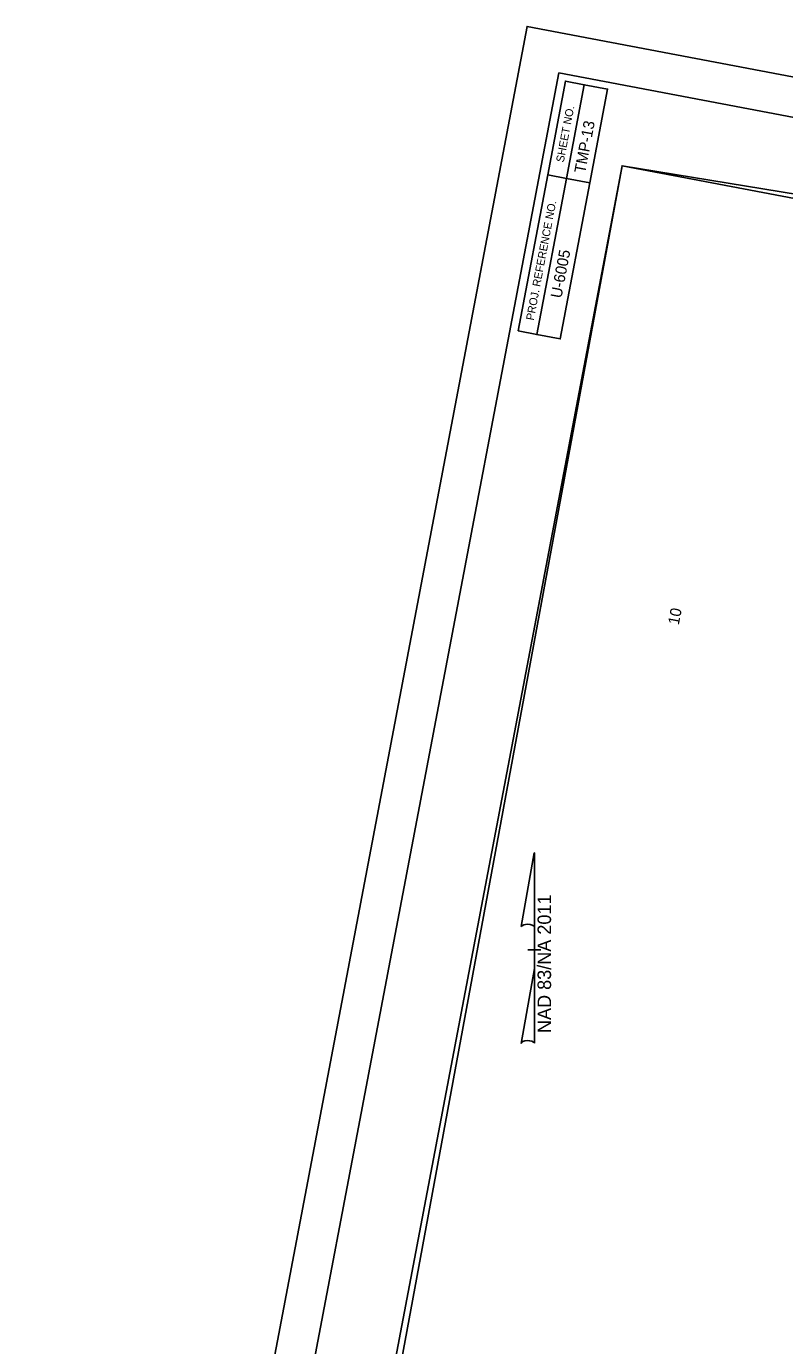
# Model space of a CAD drawing. Extents: x 1615680 to 1619687, y 899305 to 902270.
# Drawn here: x 1615680 to 1616157, y 900338 to 901168 of the extents above; entities that cross this region are included whole.
import ezdxf

# ---------------------------------------------------------------- set-up
doc = ezdxf.new("R2010")
doc.units = 0
for name, color, linetype in [('Prop Conc 2ft 6in Curb and Gutter', 7, 'Continuous'), ('Prop Conc 4in Sidewalk', 7, 'Continuous'), ('Scratch_Level_7', 7, 'Continuous'), ('Scratch_Level_8', 7, 'Continuous'), ('STAGE 3', 7, 'Continuous'), ('Stage 5', 7, 'Continuous')]:
    doc.layers.add(name, color=color, linetype=linetype)

msp = doc.modelspace()

# ---------------------------------------------------------------- linework, layer by layer
at = {"layer": 'Prop Conc 4in Sidewalk'}
msp.add_lwpolyline([(1616176.29, 901060.7), (1616848.46, 900914.27), (1616896.28, 900812.91), (1616872.94, 900688.21), (1616835.87, 900695.21), (1616753.94, 900262.18), (1616898.09, 900233.43), (1616734.79, 899562.1), (1616202.98, 899609.43), (1616198.71, 899647.14), (1615822.69, 899825.07), (1616054.34, 901080.76)], close=True, dxfattribs=at)
at = {"layer": 'Scratch_Level_7'}
msp.add_line((1616019.39, 901072.79), (1616030.58, 901131.73), dxfattribs=at)
for points in [[(1616014.55, 901139.21), (1615734.74, 899665.53), (1616766.32, 899469.67), (1617046.12, 900943.35)], [(1616019.39, 901072.79), (1616030.58, 901131.73), (1616018.79, 901133.97), (1616007.6, 901075.03)], [(1616019.39, 901072.79), (1616030.58, 901131.73), (1616045.31, 901128.94), (1616034.12, 901069.99)], [(1615988.94, 900976.78), (1616007.6, 901075.03), (1616019.39, 901072.79), (1616000.73, 900974.54)], [(1616019.39, 901072.79), (1616000.73, 900974.54), (1616015.47, 900971.74), (1616034.12, 901069.99)]]:
    msp.add_lwpolyline(points, close=True, dxfattribs=at)
at = {"layer": 'Scratch_Level_8'}
msp.add_lwpolyline([(1616054.34, 901080.76), (1615793.19, 899705.33), (1616726.52, 899528.12), (1616890.46, 900391.55), (1616774.26, 900413.61), (1616871.48, 900925.61)], close=True, dxfattribs=at)
at = {"layer": 'STAGE 3'}
for p, q in [((1615990.96, 900601.99), (1615999.16, 900648.34)), ((1615999.21, 900648.34), (1615999.16, 900648.34)), ((1615999.21, 900648.34), (1615999.16, 900648.34)), ((1615999.21, 900648.34), (1615999.21, 900600.54)), ((1615999.21, 900575.74), (1615999.21, 900601.94)), ((1615999.21, 900600.54), (1615999.21, 900601.89)), ((1615995.21, 900587.34), (1615995.16, 900587.34)), ((1615998.76, 900587.34), (1615995.21, 900587.34)), ((1615995.26, 900587.34), (1616003.26, 900587.34)), ((1615999.21, 900575.74), (1615990.86, 900528.49)), ((1615999.26, 900528.69), (1615999.21, 900575.74))]:
    msp.add_line(p, q, dxfattribs=at)
for centre, start_param, end_param in [((1615995.1, 900601.49), 0.216388, 2.908219), ((1615995.1, 900528.32), 0.201328, 3.141593)]:
    msp.add_ellipse(centre, major_axis=(4.23, -0.03), ratio=0.461098, start_param=start_param, end_param=end_param, dxfattribs=at)
at = {"layer": 'Stage 5'}
for points in [[(1616760.47, 899304.87), (1615679.78, 899510.06), (1615994.65, 901168.43), (1617075.34, 900963.24)], [(1616760.47, 899304.87), (1617075.34, 900963.24), (1615994.65, 901168.43), (1615679.78, 899510.06)]]:
    msp.add_lwpolyline(points, close=True, dxfattribs=at)

# ---------------------------------------------------------------- texts
at = {"layer": 'Prop Conc 2ft 6in Curb and Gutter'}
msp.add_text('10', height=7, rotation=79.16004, dxfattribs=at).set_placement((1616090.03, 900791.5))
at = {"layer": 'Scratch_Level_7'}
for s, height, rotation, p in [('SHEET NO.', 4.999, 79.24992, (1616017.69, 901082.61)), ('TMP-13', 7, 79.24937, (1616031.12, 901075.64)), ('PROJ. REFERENCE NO.', 4.9992, 79.24992, (1615998.81, 900983.16)), ('U-6005', 7, 79.24937, (1616016.2, 900997.05))]:
    msp.add_text(s, height=height, rotation=rotation, dxfattribs=at).set_placement(p)
at = {"layer": 'STAGE 3'}
msp.add_text('NAD 83/NA 2011', height=8.5, rotation=90, dxfattribs=at).set_placement((1616009.73, 900535.03))

doc.saveas('drawing.dxf')
